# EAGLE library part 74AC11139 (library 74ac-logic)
Dual 2 to 4 line DECODER/DEMULTIPLEXER
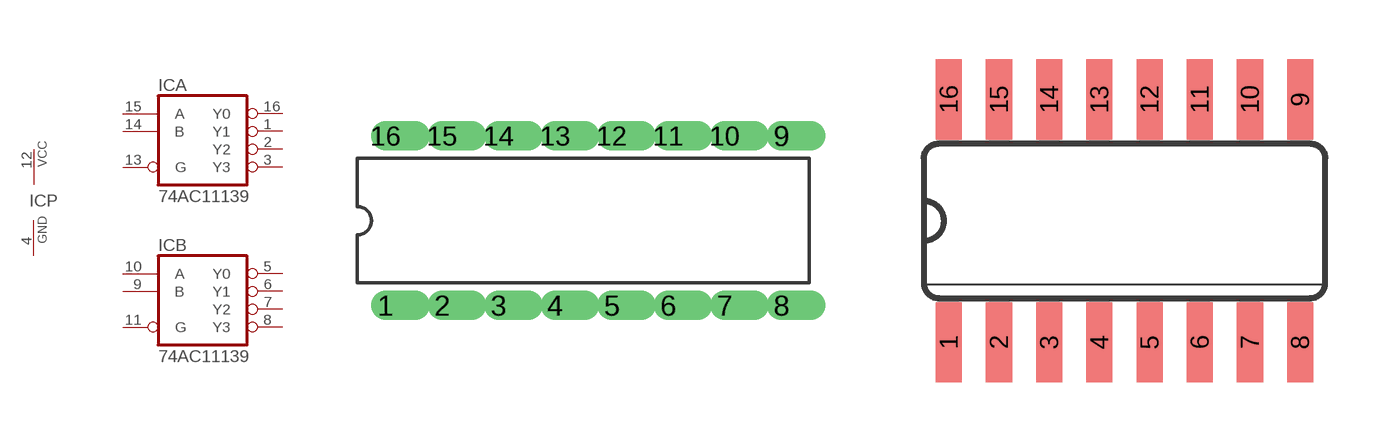
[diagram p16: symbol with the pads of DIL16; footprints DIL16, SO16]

Designator prefix IC; gates A=7411139 B=7411139 P=PWRN

## 74AC11139  [DIL16]
1  A:Y1  out
2  A:Y2  out
3  A:Y3  out
4  P:GND  pwr
5  B:Y0  out
6  B:Y1  out
7  B:Y2  out
8  B:Y3  out
9  B:B  in
10  B:A  in
11  B:G  in
12  P:VCC  pwr
13  A:G  in
14  A:B  in
15  A:A  in
16  A:Y0  out

## 74AC11139D  [SO16]
Pads as for DIL16

## Footprint DIL16 (pad centres in mm)
Dual In Line
drill 0.813 offset: 1 -8.89,-3.81; 2 -6.35,-3.81; 3 -3.81,-3.81; 4 -1.27,-3.81; 5 1.27,-3.81; 6 3.81,-3.81; 7 6.35,-3.81; 8 8.89,-3.81; 9 8.89,3.81; 10 6.35,3.81; 11 3.81,3.81; 12 1.27,3.81; 13 -1.27,3.81; 14 -3.81,3.81; 15 -6.35,3.81; 16 -8.89,3.81

## Footprint SO16 (pad centres in mm)
Small Outline package 150 mil
smd 0.66 x 2.032: 1 -4.445,-3.073; 2 -3.175,-3.073; 3 -1.905,-3.073; 4 -0.635,-3.073; 5 0.635,-3.073; 6 1.905,-3.073; 7 3.175,-3.073; 8 4.445,-3.073; 9 4.445,3.073; 10 3.175,3.073; 11 1.905,3.073; 12 0.635,3.073; 13 -0.635,3.073; 14 -1.905,3.073; 15 -3.175,3.073; 16 -4.445,3.073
